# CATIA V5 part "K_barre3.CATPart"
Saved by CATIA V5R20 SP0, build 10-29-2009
Part number: barre_3
Bounding box of the stored display mesh (mm): x -16.016 to -11.016, y -10 to -9, z -9.006 to 45.994
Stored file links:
  G:\Khaled_CFAO_2011\ST2M\ST2M_GR2\gcausse\Khaled\CAD_ThinkMotion\K_barre3.CATPart
  C:\Documents and Settings\gcausse\Bureau\video thinkmotio\assemblage_gcausse\pupitre_think.CATProduct
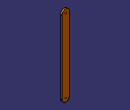
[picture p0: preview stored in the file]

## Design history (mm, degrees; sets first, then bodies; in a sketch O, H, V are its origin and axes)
Set1
  Sketch1 on Plane1, origin (0, -10, 0), H (-1, 0, 0), V (0, 0, 1)
    line L1 (11.0157, 43.4941) -> (11.0157, -6.5059)
    arc A1 centre (13.5157, -6.5059) radius 2.5 from (11.0157, -6.5059) to (16.0157, -6.5059) ccw
    point P3 (13.5157, -6.5059)
    line L2 (16.0157, -6.5059) -> (16.0157, 43.4941)
    arc A2 centre (13.5157, 43.4941) radius 2.5 from (16.0157, 43.4941) to (11.0157, 43.4941) ccw
    point P6 (13.5157, 43.4941)
    reference projected point E1 (13.5157, 43.4941) from Point1
    reference projected point E2 (13.5157, -6.5059) from Point2
    distance L2 L1 = 5
    tangency: A1 L1, L2 A1, A2 L1, A2 L2
    coincidence: P6 E1, P3 E2
Set2
  Plane1: linked copy from another document
  Point1: linked copy from another document
  Point2: linked copy from another document
Body1 (main body)
  Pad1: profile Sketch1, direction (0, 1, 0), length 1
  Sketch2 on start face of Pad1, origin (-12.6421, -10, 27.2299), H (1, 0, 0), V (0, 0, 1)
    point P1 (-0.8736, -33.7358)
    reference projected point E1 (-0.8736, -33.7358) from Point2
    coincidence: E1 P1
  Hole1: placed by Sketch2, at (-13.5157, -10, -6.5059) direction (0, 1, 0), diameter 1, depth 1
  Sketch3 on start face of Pad1, origin (-13.3695, -10, 44.7175), H (1, 0, 0), V (0, 0, 1)
    point P1 (-0.1462, -1.2234)
    reference projected point E1 (-0.1462, -1.2234) from Point1
    coincidence: P1 E1
  Hole2: placed by Sketch3, at (-13.5157, -10, 43.4941) direction (0, 1, 0), diameter 1, depth 1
